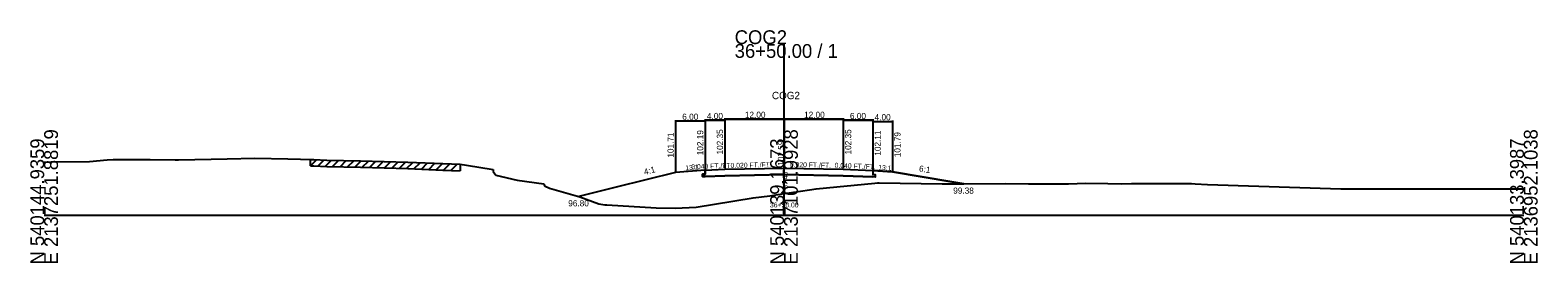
# Model space of a CAD drawing. Extents: x -13397 to 2303, y -10 to 39059.
# Drawn here: x 997.2 to 1302.8, y 12990.3 to 13037.6 of the extents above; entities that cross this region are included whole.
import ezdxf

# ---------------------------------------------------------------- set-up
doc = ezdxf.new("R2010")
doc.units = 0
for name, color, linetype in [('Level 5', 7, 'Continuous'), ('Level 53', 7, 'Continuous'), ('Level 54', 7, 'Continuous'), ('Level 55', 7, 'Continuous'), ('Level 7', 7, 'Continuous'), ('RD_GPK_XS_Cell', 7, 'Continuous'), ('RD_XS_EwShp', 7, 'Continuous'), ('RD_XS_ExGround', 7, 'Continuous'), ('RD_XS_ExPaveRet', 7, 'Continuous'), ('RD_XS_Pave', 7, 'Continuous'), ('RD_XS_TX_Baseline', 7, 'Continuous'), ('RD_XS_TX_Elev_EX', 7, 'Continuous'), ('RD_XS_TX_Elev_PR', 7, 'Continuous'), ('RD_XS_TX_Station', 7, 'Continuous')]:
    doc.layers.add(name, color=color, linetype=linetype)

msp = doc.modelspace()

# ---------------------------------------------------------------- linework, layer by layer
at = {"layer": 'Level 5'}
for p, q in [((1134, 13008.36), (1133.5, 13008.34)), ((1133.5, 13008.34), (1133.5, 13007.84)), ((1133.5, 13007.84), (1134, 13007.86)), ((1134, 13009.19), (1134, 13008.36)), ((1138, 13008.02), (1134, 13007.86)), ((1138, 13008.02), (1134, 13007.86)), ((1138, 13008.02), (1134, 13007.86)), ((1134, 13007.86), (1138, 13008.02)), ((1150, 13008.26), (1138, 13008.02)), ((1150, 13008.26), (1138, 13008.02)), ((1150, 13008.26), (1138, 13008.02)), ((1138, 13008.02), (1150, 13008.26)), ((1138, 13008.02), (1150, 13008.26)), ((1162, 13008.02), (1150, 13008.26)), ((1162, 13008.02), (1150, 13008.26)), ((1150, 13008.26), (1162, 13008.02)), ((1150, 13008.26), (1162, 13008.02)), ((1150, 13008.26), (1162, 13008.02)), ((1168, 13007.78), (1162, 13008.02)), ((1162, 13008.02), (1168, 13007.78)), ((1162, 13008.02), (1168, 13007.78)), ((1162, 13008.02), (1168, 13007.78)), ((1168, 13009.11), (1168, 13008.28)), ((1168, 13008.28), (1168.5, 13008.26)), ((1168.5, 13007.76), (1168, 13007.78)), ((1168.5, 13008.26), (1168.5, 13007.76))]:
    msp.add_line(p, q, dxfattribs=at)
at = {"layer": 'Level 54'}
for p, q in [((1128, 13019.34), (1128, 13008.91)), ((1134, 13019.14), (1128, 13019.14)), ((1134, 13019.5), (1134, 13009.39)), ((1134, 13019.5), (1134, 13009.39)), ((1134, 13019.5), (1134, 13009.39)), ((1134, 13019.5), (1134, 13009.39)), ((1134, 13019.34), (1134, 13009.39)), ((1134, 13019.3), (1138, 13019.3)), ((1134, 13019.3), (1138, 13019.3)), ((1134, 13019.3), (1138, 13019.3)), ((1138, 13019.3), (1134, 13019.3)), ((1138, 13019.74), (1138, 13009.55)), ((1138, 13019.74), (1138, 13009.55)), ((1138, 13019.74), (1138, 13009.55)), ((1138, 13019.74), (1138, 13009.55)), ((1138, 13019.74), (1138, 13009.55)), ((1138, 13019.54), (1150, 13019.54)), ((1138, 13019.54), (1150, 13019.54)), ((1138, 13019.54), (1150, 13019.54)), ((1150, 13019.54), (1138, 13019.54)), ((1150, 13019.54), (1138, 13019.54)), ((1138, 13019.5), (1138, 13009.55)), ((1138, 13019.5), (1138, 13009.55)), ((1138, 13019.5), (1138, 13009.55)), ((1138, 13019.5), (1138, 13009.55)), ((1150, 13019.74), (1150, 13009.79)), ((1150, 13019.74), (1150, 13009.79)), ((1150, 13019.74), (1150, 13009.79)), ((1150, 13019.74), (1150, 13009.79)), ((1150, 13019.74), (1150, 13009.79)), ((1150, 13019.74), (1150, 13009.79)), ((1150, 13019.74), (1150, 13009.79)), ((1150, 13019.74), (1150, 13009.79)), ((1150, 13019.74), (1150, 13009.79)), ((1150, 13019.74), (1150, 13009.79)), ((1150, 13019.54), (1162, 13019.54)), ((1150, 13019.54), (1162, 13019.54)), ((1162, 13019.54), (1150, 13019.54)), ((1162, 13019.54), (1150, 13019.54)), ((1162, 13019.54), (1150, 13019.54)), ((1162, 13019.74), (1162, 13009.55)), ((1162, 13019.74), (1162, 13009.55)), ((1162, 13019.74), (1162, 13009.55)), ((1162, 13019.74), (1162, 13009.55)), ((1162, 13019.74), (1162, 13009.55)), ((1162, 13019.5), (1162, 13009.55)), ((1162, 13019.5), (1162, 13009.55)), ((1162, 13019.5), (1162, 13009.55)), ((1162, 13019.5), (1162, 13009.55)), ((1162, 13019.3), (1168, 13019.3)), ((1168, 13019.3), (1162, 13019.3)), ((1168, 13019.3), (1162, 13019.3)), ((1168, 13019.3), (1162, 13019.3)), ((1168, 13019.5), (1168, 13009.31)), ((1168, 13019.5), (1168, 13009.31)), ((1168, 13019.5), (1168, 13009.31)), ((1168, 13019.5), (1168, 13009.31)), ((1168, 13019.26), (1168, 13009.31)), ((1168, 13019.06), (1172, 13019.06)), ((1172, 13019.26), (1172, 13008.99))]:
    msp.add_line(p, q, dxfattribs=at)
at = {"layer": 'Level 7'}
for p, q in [((1128, 13008.71), (1116, 13005.71)), ((1134, 13009.19), (1128, 13008.71)), ((1168, 13009.11), (1172, 13008.79)), ((1172, 13008.79), (1184, 13006.79)), ((1184, 13006.79), (1186.48, 13006.38)), ((1116, 13005.71), (1108.38, 13003.8))]:
    msp.add_line(p, q, dxfattribs=at)
at = {"layer": 'RD_GPK_XS_Cell'}
for p, q in [((1150, 13000), (1150, 13034.79)), ((1000, 13000), (1150, 13000)), ((1150, 13000), (1300, 13000))]:
    msp.add_line(p, q, dxfattribs=at)
at = {"layer": 'RD_XS_EwShp'}
msp.add_lwpolyline([(1138, 13008.02), (1134, 13007.86), (1133.5, 13007.84), (1133.5, 13008.34), (1134, 13008.36), (1134, 13009.19), (1128, 13008.71), (1116, 13005.71), (1108.38, 13003.8), (1108.62, 13003.73), (1112.48, 13002.32), (1113.7, 13002.11), (1114.06, 13002.1), (1124.1, 13001.53), (1127.91, 13001.47), (1132.2, 13001.62), (1135.93, 13002.24), (1143.75, 13003.57), (1147.14, 13003.95), (1150, 13004.4), (1151.97, 13004.71), (1156.54, 13005.39), (1168.42, 13006.52), (1168.93, 13006.56), (1169.32, 13006.57), (1173.54, 13006.49), (1182.1, 13006.38), (1183.82, 13006.35), (1186.48, 13006.38), (1184, 13006.79), (1172, 13008.79), (1168, 13009.11), (1168, 13008.28), (1168.5, 13008.26), (1168.5, 13007.76), (1168, 13007.78), (1162, 13008.02), (1150, 13008.26)], close=True, dxfattribs=at)
at = {"layer": 'RD_XS_ExGround'}
for p, q in [((1000, 13010.82), (1001.42, 13010.83)), ((1001.42, 13010.83), (1009.17, 13010.92)), ((1009.17, 13010.92), (1012.78, 13011.23)), ((1012.78, 13011.23), (1014.02, 13011.3)), ((1014.02, 13011.3), (1017.75, 13011.32)), ((1017.75, 13011.32), (1021.48, 13011.32)), ((1021.48, 13011.32), (1026.53, 13011.29)), ((1026.53, 13011.29), (1027.22, 13011.29)), ((1027.22, 13011.29), (1033.85, 13011.43)), ((1033.85, 13011.43), (1037.1, 13011.47)), ((1037.1, 13011.47), (1042.69, 13011.6)), ((1042.69, 13011.6), (1049.41, 13011.46)), ((1049.41, 13011.46), (1051.97, 13011.4)), ((1051.97, 13011.4), (1053.98, 13011.34)), ((1053.98, 13011.34), (1054.65, 13011.32)), ((1054.65, 13011.32), (1057.34, 13011.22)), ((1057.34, 13011.22), (1064.13, 13011.05)), ((1064.13, 13011.05), (1073.74, 13010.78)), ((1073.74, 13010.78), (1080.82, 13010.49)), ((1080.82, 13010.49), (1084.34, 13010.35)), ((1084.34, 13010.35), (1085.65, 13010.16)), ((1085.65, 13010.16), (1091.05, 13009.3)), ((1091.05, 13009.3), (1091.06, 13008.89)), ((1091.06, 13008.89), (1091.6, 13008.16)), ((1091.6, 13008.16), (1095.87, 13007.16)), ((1095.87, 13007.16), (1101.33, 13006.4)), ((1101.33, 13006.4), (1101.47, 13005.96)), ((1101.47, 13005.96), (1102.43, 13005.51)), ((1102.43, 13005.51), (1108.62, 13003.73)), ((1108.62, 13003.73), (1112.48, 13002.32)), ((1143.75, 13003.57), (1147.14, 13003.95)), ((1147.14, 13003.95), (1150, 13004.4)), ((1150, 13004.4), (1151.97, 13004.71)), ((1151.97, 13004.71), (1156.54, 13005.39)), ((1156.54, 13005.39), (1168.42, 13006.52)), ((1168.42, 13006.52), (1168.93, 13006.56)), ((1168.93, 13006.56), (1169.32, 13006.57)), ((1169.32, 13006.57), (1173.54, 13006.49)), ((1173.54, 13006.49), (1182.1, 13006.38)), ((1182.1, 13006.38), (1183.82, 13006.35)), ((1183.82, 13006.35), (1194.88, 13006.47)), ((1194.88, 13006.47), (1199.56, 13006.38)), ((1199.56, 13006.38), (1207.67, 13006.4)), ((1207.67, 13006.4), (1211.19, 13006.52)), ((1211.19, 13006.52), (1215.66, 13006.46)), ((1215.66, 13006.46), (1218.35, 13006.35)), ((1218.35, 13006.35), (1220.45, 13006.43)), ((1220.45, 13006.43), (1231.81, 13006.42)), ((1231.81, 13006.42), (1232.6, 13006.43)), ((1232.6, 13006.43), (1233.38, 13006.37)), ((1233.38, 13006.37), (1235.86, 13006.28)), ((1235.86, 13006.28), (1262.87, 13005.39)), ((1262.87, 13005.39), (1269.66, 13005.39)), ((1269.66, 13005.39), (1270.26, 13005.39)), ((1270.26, 13005.39), (1300, 13005.39)), ((1112.48, 13002.32), (1113.7, 13002.11)), ((1113.7, 13002.11), (1114.06, 13002.1)), ((1114.06, 13002.1), (1124.1, 13001.53)), ((1124.1, 13001.53), (1127.91, 13001.47)), ((1127.91, 13001.47), (1132.2, 13001.62)), ((1132.2, 13001.62), (1135.93, 13002.24)), ((1135.93, 13002.24), (1143.75, 13003.57))]:
    msp.add_line(p, q, dxfattribs=at)
at = {"layer": 'RD_XS_ExPaveRet'}
for p, q in [((1053.98, 13010.04), (1053.98, 13011.34)), ((1053.98, 13010.04), (1055.25, 13011.3)), ((1053.98, 13010.04), (1054.65, 13010.02)), ((1054.65, 13010.02), (1057.34, 13009.92)), ((1055.48, 13009.99), (1056.74, 13011.24)), ((1056.98, 13009.93), (1058.25, 13011.2)), ((1057.34, 13009.92), (1064.13, 13009.75)), ((1058.48, 13009.89), (1059.75, 13011.16)), ((1059.98, 13009.85), (1061.25, 13011.12)), ((1061.48, 13009.81), (1062.75, 13011.08)), ((1062.98, 13009.78), (1064.25, 13011.04)), ((1064.48, 13009.74), (1065.75, 13011)), ((1065.98, 13009.7), (1067.25, 13010.96)), ((1067.48, 13009.66), (1068.75, 13010.92)), ((1068.98, 13009.61), (1070.25, 13010.88)), ((1070.48, 13009.57), (1071.75, 13010.84)), ((1071.98, 13009.53), (1073.25, 13010.8)), ((1073.48, 13009.49), (1074.74, 13010.74)), ((1074.98, 13009.43), (1076.23, 13010.68)), ((1076.48, 13009.37), (1077.73, 13010.62)), ((1077.98, 13009.31), (1079.23, 13010.56)), ((1079.48, 13009.25), (1080.73, 13010.5)), ((1080.98, 13009.19), (1082.23, 13010.43)), ((1082.48, 13009.12), (1083.73, 13010.37)), ((1084.34, 13010.35), (1084.34, 13009.05)), ((1064.13, 13009.75), (1073.74, 13009.48)), ((1073.74, 13009.48), (1080.82, 13009.19)), ((1080.82, 13009.19), (1084.34, 13009.05))]:
    msp.add_line(p, q, dxfattribs=at)
at = {"layer": 'RD_XS_Pave'}
for p, q in [((1134, 13009.19), (1138, 13009.35)), ((1138, 13009.35), (1150, 13009.59)), ((1150, 13009.59), (1162, 13009.35)), ((1162, 13009.35), (1168, 13009.11))]:
    msp.add_line(p, q, dxfattribs=at)

# ---------------------------------------------------------------- texts
at = {"layer": 'Level 53'}
for s, rotation, p in [('101.71', 90, (1127.63, 13011.71)), ('102.19', 90, (1133.63, 13012.19)), ('102.35', 90, (1137.63, 13012.35)), ('102.35', 90, (1137.63, 13012.35)), ('102.35', 90, (1137.63, 13012.35)), ('102.35', 90, (1163.63, 13012.35)), ('102.35', 90, (1163.63, 13012.35)), ('102.35', 90, (1163.63, 13012.35)), ('102.11', 90, (1169.62, 13012.11)), ('101.79', 90, (1173.62, 13011.79)), ('4:1', 14.0362, (1121.76, 13008.18)), ('6:1', 350.5377, (1177.3, 13008.92))]:
    msp.add_text(s, height=1.25, rotation=rotation, dxfattribs=at).set_placement(p)
for s, p in [('99.38', (1184.31, 13004.38)), ('96.80', (1106.25, 13001.8))]:
    msp.add_text(s, height=1.25, dxfattribs=at).set_placement(p)
at = {"layer": 'Level 54'}
for s, p in [('6.00', (1129.37, 13019.39)), ('4.00', (1134.37, 13019.55)), ('4.00', (1134.37, 13019.55)), ('4.00', (1134.37, 13019.55)), ('4.00', (1134.37, 13019.55)), ('12.00', (1142.07, 13019.79)), ('12.00', (1142.07, 13019.79)), ('12.00', (1142.07, 13019.79)), ('12.00', (1142.07, 13019.79)), ('12.00', (1142.07, 13019.79)), ('12.00', (1154.07, 13019.79)), ('12.00', (1154.07, 13019.79)), ('12.00', (1154.07, 13019.79)), ('12.00', (1154.07, 13019.79)), ('12.00', (1154.07, 13019.79)), ('6.00', (1163.37, 13019.55)), ('6.00', (1163.37, 13019.55)), ('6.00', (1163.37, 13019.55)), ('6.00', (1163.37, 13019.55)), ('4.00', (1168.37, 13019.31))]:
    msp.add_text(s, height=1.25, dxfattribs=at).set_placement(p)
at = {"layer": 'Level 55'}
for s, rotation, p in [('13:1', 4.5739, (1130.03, 13009.12)), ('0.040 FT./FT.', 2.2906, (1131.22, 13009.33)), ('0.040 FT./FT.', 2.2906, (1131.22, 13009.33)), ('0.040 FT./FT.', 2.2906, (1131.22, 13009.33)), ('0.040 FT./FT.', 2.2906, (1131.22, 13009.33)), ('0.020 FT./FT.', 1.1458, (1139.17, 13009.62)), ('0.020 FT./FT.', 1.1458, (1139.17, 13009.62)), ('0.020 FT./FT.', 1.1458, (1139.17, 13009.62)), ('0.020 FT./FT.', 1.1458, (1139.17, 13009.62)), ('0.020 FT./FT.', 1.1458, (1139.17, 13009.62)), ('0.020 FT./FT.', 358.8542, (1151.18, 13009.82)), ('0.020 FT./FT.', 358.8542, (1151.18, 13009.82)), ('0.020 FT./FT.', 358.8542, (1151.18, 13009.82)), ('0.020 FT./FT.', 358.8542, (1151.18, 13009.82)), ('0.020 FT./FT.', 358.8542, (1151.18, 13009.82)), ('0.040 FT./FT.', 357.7094, (1160.24, 13009.67)), ('0.040 FT./FT.', 357.7094, (1160.24, 13009.67)), ('0.040 FT./FT.', 357.7094, (1160.24, 13009.67)), ('0.040 FT./FT.', 357.7094, (1160.24, 13009.67)), ('13:1', 355.4261, (1169.07, 13009.28))]:
    msp.add_text(s, height=1, rotation=rotation, dxfattribs=at).set_placement(p)
at = {"layer": 'RD_GPK_XS_Cell'}
for s, p in [('COG2', (1140, 13034.79)), ('36+50.00 / 1', (1140, 13031.99))]:
    msp.add_text(s, height=2.8, dxfattribs=at).set_placement(p)
for s, p in [('E 2137251.8819', (1002.8, 12990)), ('E 2137101.9928', (1152.8, 12990)), ('E 2136952.1038', (1302.8, 12990)), ('N 540144.9359', (1000, 12990)), ('N 540139.1673', (1150, 12990)), ('N 540133.3987', (1300, 12990))]:
    msp.add_text(s, height=2.8, rotation=90, dxfattribs=at).set_placement(p)
at = {"layer": 'RD_XS_TX_Baseline'}
msp.add_text('COG2', height=1.5, dxfattribs=at).set_placement((1147.55, 13023.59))
at = {"layer": 'RD_XS_TX_Elev_EX'}
msp.add_text('97.40', height=1, rotation=90, dxfattribs=at).set_placement((1150.75, 13005.4))
at = {"layer": 'RD_XS_TX_Elev_PR'}
msp.add_text(' 102.59', height=1.25, rotation=90, dxfattribs=at).set_placement((1150, 13009.59))
at = {"layer": 'RD_XS_TX_Station'}
msp.add_text('36+50.00', height=1, dxfattribs=at).set_placement((1147.15, 13001.59))

doc.saveas('drawing.dxf')
